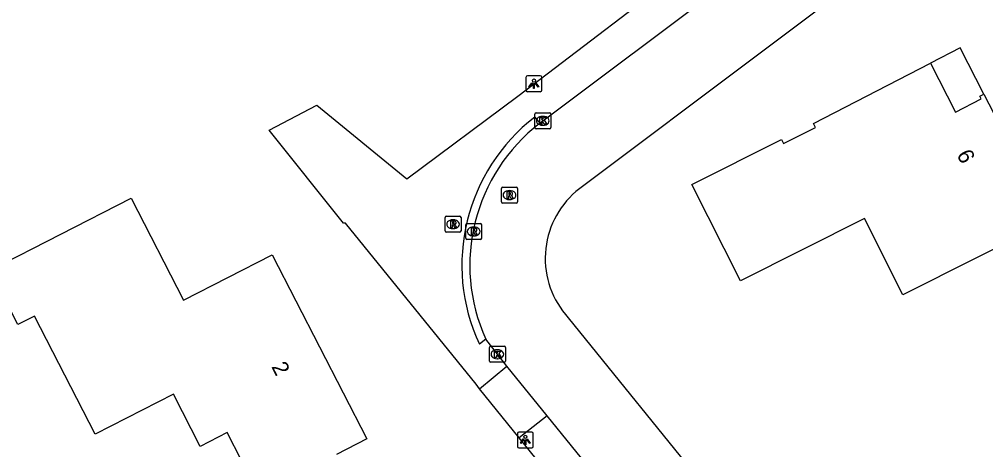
# Model space of a CAD drawing. Extents: x 162722 to 165099, y 384721 to 386283.
# Drawn here: x 163645.1 to 163705.8, y 384903 to 384930.1 of the extents above; entities that cross this region are included whole.
import ezdxf

# ---------------------------------------------------------------- set-up
doc = ezdxf.new("R2010")
doc.units = 0
for name, color, linetype in [('IMGEO_Kolk', 7, 'Continuous'), ('IMGEO_Lichtpunt', 7, 'Continuous'), ('IMGEO_Pand', 7, 'Continuous'), ('IMGEO_Pand_nummerreeks', 7, 'Continuous'), ('IMGEO_Pand_overbouw', 7, 'Continuous'), ('IMGEO_Rijbaan_lokaal_open', 7, 'Continuous'), ('IMGEO_Rioolput', 7, 'Continuous'), ('IMGEO_Voetpad_open', 7, 'Continuous')]:
    doc.layers.add(name, color=color, linetype=linetype)

msp = doc.modelspace()

# ---------------------------------------------------------------- linework, layer by layer
at = {"layer": 'IMGEO_Kolk'}
for p, q in [((163677.447, 384923.271), (163677.447, 384924.123)), ((163677.522, 384924.197), (163678.374, 384924.197)), ((163678.448, 384924.123), (163678.448, 384923.271)), ((163677.935, 384923.977), (163677.96, 384923.977)), ((163678.374, 384923.197), (163677.522, 384923.197)), ((163677.958, 384923.417), (163677.933, 384923.417)), ((163674.671, 384909.515), (163675.523, 384909.515)), ((163674.596, 384908.589), (163674.596, 384909.441)), ((163675.084, 384909.295), (163675.109, 384909.295)), ((163675.597, 384909.441), (163675.597, 384908.589)), ((163675.523, 384908.515), (163674.671, 384908.515)), ((163675.107, 384908.735), (163675.082, 384908.735))]:
    msp.add_line(p, q, dxfattribs=at)
for points in [[(163677.447, 384923.271), (163677.447, 384924.123)], [(163677.522, 384924.197), (163678.374, 384924.197)], [(163678.448, 384924.123), (163678.448, 384923.271)], [(163677.768, 384923.897), (163677.891, 384923.897), (163677.891, 384923.746), (163678.021, 384923.897), (163678.185, 384923.897), (163678.039, 384923.746), (163678.192, 384923.497), (163678.04, 384923.497), (163677.955, 384923.661), (163677.891, 384923.594), (163677.891, 384923.497), (163677.768, 384923.497), (163677.768, 384923.897)], [(163678.374, 384923.197), (163677.522, 384923.197)], [(163674.671, 384909.515), (163675.523, 384909.515)], [(163674.596, 384908.589), (163674.596, 384909.441)], [(163674.917, 384909.215), (163675.04, 384909.215), (163675.04, 384909.064), (163675.17, 384909.215), (163675.334, 384909.215), (163675.188, 384909.064), (163675.341, 384908.815), (163675.189, 384908.815), (163675.104, 384908.979), (163675.04, 384908.912), (163675.04, 384908.815), (163674.917, 384908.815), (163674.917, 384909.215)], [(163675.597, 384909.441), (163675.597, 384908.589)], [(163675.523, 384908.515), (163674.671, 384908.515)]]:
    msp.add_lwpolyline(points, dxfattribs=at)
for centre, start, end in [((163677.524, 384924.121), 91.55205, 178.44795), ((163677.524, 384924.121), 91.55205, 178.44795), ((163678.372, 384924.121), 1.55205, 88.44795), ((163678.372, 384924.121), 1.55205, 88.44795), ((163677.524, 384923.273), 181.55205, 268.44795), ((163677.524, 384923.273), 181.55205, 268.44795), ((163678.372, 384923.273), 271.55205, 358.44795), ((163678.372, 384923.273), 271.55205, 358.44795), ((163674.673, 384909.439), 91.55205, 178.44795), ((163674.673, 384909.439), 91.55205, 178.44795), ((163675.521, 384909.439), 1.55205, 88.44795), ((163675.521, 384909.439), 1.55205, 88.44795), ((163674.673, 384908.591), 181.55205, 268.44795), ((163674.673, 384908.591), 181.55205, 268.44795), ((163675.521, 384908.591), 271.55205, 358.44795), ((163675.521, 384908.591), 271.55205, 358.44795)]:
    msp.add_arc(centre, 0.0765, start, end, dxfattribs=at)
for centre, major_axis, ratio, start_param, end_param in [((163677.934, 384923.697), (-0.387, 0.002), 0.722429, 4.712389, 7.853982), ((163677.959, 384923.697), (-0.39, 0.002), 0.717154, 1.570796, 4.712389), ((163675.083, 384909.015), (-0.387, 0.002), 0.722429, 4.712389, 7.853982), ((163675.108, 384909.015), (-0.39, 0.002), 0.717154, 1.570796, 4.712389)]:
    msp.add_ellipse(centre, major_axis=major_axis, ratio=ratio, start_param=start_param, end_param=end_param, dxfattribs=at)
at = {"layer": 'IMGEO_Lichtpunt'}
for p, q in [((163677.793, 384926.527), (163676.985, 384926.527)), ((163677.793, 384926.527), (163676.985, 384926.527)), ((163676.891, 384926.432), (163676.891, 384925.625)), ((163676.891, 384926.432), (163676.891, 384925.625)), ((163677.887, 384925.625), (163677.887, 384926.432)), ((163677.887, 384925.625), (163677.887, 384926.432)), ((163676.985, 384925.531), (163677.793, 384925.531)), ((163676.985, 384925.531), (163677.793, 384925.531)), ((163677.253, 384904.119), (163676.445, 384904.119)), ((163677.253, 384904.119), (163676.445, 384904.119)), ((163676.351, 384904.024), (163676.351, 384903.217)), ((163676.351, 384904.024), (163676.351, 384903.217)), ((163677.347, 384903.217), (163677.347, 384904.024)), ((163677.347, 384903.217), (163677.347, 384904.024)), ((163676.445, 384903.123), (163677.253, 384903.123)), ((163676.445, 384903.123), (163677.253, 384903.123))]:
    msp.add_line(p, q, dxfattribs=at)
for points in [[(163677.265, 384926.096), (163677.304, 384926.068), (163677.116, 384925.806), (163677.078, 384925.833), (163677.265, 384926.096)], [(163677.367, 384926.048), (163677.414, 384926.048), (163677.414, 384925.726), (163677.367, 384925.726), (163677.367, 384926.048)], [(163677.477, 384926.068), (163677.515, 384926.095), (163677.702, 384925.833), (163677.663, 384925.805), (163677.477, 384926.068)], [(163676.725, 384903.688), (163676.764, 384903.66), (163676.576, 384903.398), (163676.538, 384903.425), (163676.725, 384903.688)], [(163676.827, 384903.64), (163676.874, 384903.64), (163676.874, 384903.318), (163676.827, 384903.318), (163676.827, 384903.64)], [(163676.937, 384903.66), (163676.975, 384903.687), (163677.162, 384903.425), (163677.123, 384903.397), (163676.937, 384903.66)]]:
    msp.add_lwpolyline(points, dxfattribs=at)
for centre in [(163677.39, 384926.23), (163676.85, 384903.822)]:
    msp.add_circle(centre, 0.0994, dxfattribs=at)
for centre, start, end in [((163676.985, 384926.432), 90, 180), ((163676.985, 384926.432), 90, 180), ((163677.793, 384926.432), 0, 90), ((163677.793, 384926.432), 0, 90), ((163676.985, 384925.625), 180, 270), ((163676.985, 384925.625), 180, 270), ((163677.793, 384925.625), 270, 0), ((163677.793, 384925.625), 270, 360), ((163676.445, 384904.024), 90, 180), ((163676.445, 384904.024), 90, 180), ((163677.253, 384904.024), 0, 90), ((163677.253, 384904.024), 0, 90), ((163676.445, 384903.217), 180, 270), ((163676.445, 384903.217), 180, 270), ((163677.253, 384903.217), 270, 0), ((163677.253, 384903.217), 270, 360)]:
    msp.add_arc(centre, 0.0946, start, end, dxfattribs=at)
at = {"layer": 'IMGEO_Pand'}
for points in [[(163700.576, 384912.76), (163698.165, 384917.548), (163690.367, 384913.622), (163687.312, 384919.691), (163692.94, 384922.524), (163693.071, 384922.265), (163695.08, 384923.277), (163694.949, 384923.535), (163702.295, 384927.318), (163703.875, 384924.249), (163705.494, 384925.083), (163705.411, 384925.243), (163705.661, 384925.37), (163709.772, 384917.389), (163700.576, 384912.76)], [(163659.924, 384900.579), (163658.124, 384904.091), (163656.423, 384903.219), (163654.742, 384906.499), (163649.828, 384903.98), (163646.017, 384911.417), (163644.976, 384910.883), (163643.226, 384914.296), (163652.091, 384918.839), (163655.38, 384912.42), (163660.955, 384915.277), (163666.893, 384903.689), (163664.992, 384902.715)]]:
    msp.add_lwpolyline(points, dxfattribs=at)
at = {"layer": 'IMGEO_Pand_overbouw'}
msp.add_lwpolyline([(163704.162, 384928.28), (163702.295, 384927.318), (163703.875, 384924.249), (163705.494, 384925.083), (163705.411, 384925.243), (163705.661, 384925.37)], close=True, dxfattribs=at)
at = {"layer": 'IMGEO_Rijbaan_lokaal_open'}
for points in [[(163677.764, 384923.542), (163677.956, 384923.704), (163689.321, 384932.243), (163699.74, 384940.081), (163700.468, 384940.621)], [(163703.684, 384937.056), (163680.028, 384919.248)], [(163679.55, 384911.309), (163688.362, 384900.411), (163688.262, 384900.349), (163695.837, 384890.93), (163705.052, 384879.586)], [(163675.679, 384908.261), (163674.367, 384909.96)], [(163678.232, 384905.132), (163675.679, 384908.261)], [(163688.814, 384892.037), (163684.328, 384897.597), (163678.232, 384905.132)]]:
    msp.add_lwpolyline(points, dxfattribs=at)
for centre, radius, start, end in [((163684.63, 384914.609), 11.267, 127.54713, 204.36847), ((163683.649, 384915.046), 5.547, 130.74979, 222.35907)]:
    msp.add_arc(centre, radius, start, end, dxfattribs=at)
at = {"layer": 'IMGEO_Rioolput'}
for p, q in [((163675.355, 384918.598), (163675.355, 384919.45)), ((163675.43, 384919.524), (163676.282, 384919.524)), ((163675.843, 384919.304), (163675.868, 384919.304)), ((163676.356, 384919.45), (163676.356, 384918.598)), ((163675.866, 384918.744), (163675.841, 384918.744)), ((163676.282, 384918.524), (163675.43, 384918.524)), ((163671.809, 384916.767), (163671.809, 384917.619)), ((163671.884, 384917.693), (163672.736, 384917.693)), ((163672.297, 384917.473), (163672.322, 384917.473)), ((163672.81, 384917.619), (163672.81, 384916.767)), ((163672.32, 384916.913), (163672.295, 384916.913)), ((163673.106, 384916.309), (163673.106, 384917.161)), ((163673.181, 384917.235), (163674.033, 384917.235)), ((163673.594, 384917.015), (163673.619, 384917.015)), ((163674.107, 384917.161), (163674.107, 384916.309)), ((163672.736, 384916.693), (163671.884, 384916.693)), ((163674.033, 384916.235), (163673.181, 384916.235)), ((163673.617, 384916.455), (163673.592, 384916.455))]:
    msp.add_line(p, q, dxfattribs=at)
for points in [[(163675.355, 384918.598), (163675.355, 384919.45)], [(163675.43, 384919.524), (163676.282, 384919.524)], [(163675.944, 384919.222), (163675.692, 384919.224), (163675.692, 384918.824)], [(163676.356, 384919.45), (163676.356, 384918.598)], [(163675.692, 384918.824), (163675.816, 384918.824), (163675.816, 384918.986), (163675.827, 384918.986)], [(163675.87, 384919.143), (163675.816, 384919.143), (163675.816, 384919.062)], [(163675.816, 384919.062), (163675.868, 384919.062)], [(163675.874, 384918.957), (163675.945, 384918.824), (163676.085, 384918.824), (163676.02, 384918.95)], [(163676.282, 384918.524), (163675.43, 384918.524)], [(163671.809, 384916.767), (163671.809, 384917.619)], [(163671.884, 384917.693), (163672.736, 384917.693)], [(163672.398, 384917.391), (163672.146, 384917.393), (163672.146, 384916.993)], [(163672.81, 384917.619), (163672.81, 384916.767)], [(163672.146, 384916.993), (163672.27, 384916.993), (163672.27, 384917.155), (163672.281, 384917.155)], [(163672.324, 384917.312), (163672.27, 384917.312), (163672.27, 384917.231)], [(163672.27, 384917.231), (163672.322, 384917.231)], [(163672.328, 384917.126), (163672.399, 384916.993), (163672.539, 384916.993), (163672.474, 384917.119)], [(163673.106, 384916.309), (163673.106, 384917.161)], [(163673.181, 384917.235), (163674.033, 384917.235)], [(163673.695, 384916.933), (163673.443, 384916.935), (163673.443, 384916.535)], [(163673.621, 384916.854), (163673.567, 384916.854), (163673.567, 384916.773)], [(163674.107, 384917.161), (163674.107, 384916.309)], [(163672.736, 384916.693), (163671.884, 384916.693)], [(163674.033, 384916.235), (163673.181, 384916.235)], [(163673.443, 384916.535), (163673.567, 384916.535), (163673.567, 384916.697), (163673.578, 384916.697)], [(163673.567, 384916.773), (163673.619, 384916.773)], [(163673.625, 384916.668), (163673.696, 384916.535), (163673.836, 384916.535), (163673.771, 384916.661)]]:
    msp.add_lwpolyline(points, dxfattribs=at)
for centre, radius, start, end in [((163675.432, 384919.448), 0.0765, 91.55205, 178.44795), ((163675.432, 384919.448), 0.0765, 91.55205, 178.44795), ((163675.943, 384919.112), 0.109, 350.36119, 89.41601), ((163676.28, 384919.448), 0.0765, 1.55205, 88.44795), ((163676.28, 384919.448), 0.0765, 1.55205, 88.44795), ((163675.826, 384918.933), 0.0533, 26.02933, 88.69889), ((163675.852, 384919.251), 0.19, 274.7715, 282.96867), ((163675.876, 384919.047), 0.0964, 77.00612, 93.18647), ((163675.89, 384919.104), 0.0378, 276.66336, 79.67722), ((163675.941, 384919.112), 0.112, 277.58423, 350.98172), ((163675.925, 384918.897), 0.108, 29.51342, 73.79051), ((163675.432, 384918.6), 0.0765, 181.55205, 268.44795), ((163675.432, 384918.6), 0.0765, 181.55205, 268.44795), ((163676.28, 384918.6), 0.0765, 271.55205, 358.44795), ((163676.28, 384918.6), 0.0765, 271.55205, 358.44795), ((163671.886, 384917.617), 0.0765, 91.55205, 178.44795), ((163671.886, 384917.617), 0.0765, 91.55205, 178.44795), ((163672.397, 384917.281), 0.109, 350.36119, 89.41601), ((163672.734, 384917.617), 0.0765, 1.55205, 88.44795), ((163672.734, 384917.617), 0.0765, 1.55205, 88.44795), ((163672.28, 384917.102), 0.0533, 26.02933, 88.69889), ((163672.306, 384917.42), 0.19, 274.7715, 282.96867), ((163672.33, 384917.216), 0.0964, 77.00612, 93.18647), ((163672.344, 384917.273), 0.0378, 276.66336, 79.67722), ((163672.395, 384917.281), 0.112, 277.58423, 350.98172), ((163672.379, 384917.066), 0.108, 29.51342, 73.79051), ((163673.183, 384917.159), 0.0765, 91.55205, 178.44795), ((163673.183, 384917.159), 0.0765, 91.55205, 178.44795), ((163673.627, 384916.758), 0.0964, 77.00612, 93.18647), ((163673.641, 384916.815), 0.0378, 276.66336, 79.67722), ((163673.694, 384916.823), 0.109, 350.36119, 89.41601), ((163673.692, 384916.823), 0.112, 277.58423, 350.98172), ((163674.031, 384917.159), 0.0765, 1.55205, 88.44795), ((163674.031, 384917.159), 0.0765, 1.55205, 88.44795), ((163671.886, 384916.769), 0.0765, 181.55205, 268.44795), ((163671.886, 384916.769), 0.0765, 181.55205, 268.44795), ((163672.734, 384916.769), 0.0765, 271.55205, 358.44795), ((163672.734, 384916.769), 0.0765, 271.55205, 358.44795), ((163673.183, 384916.311), 0.0765, 181.55205, 268.44795), ((163673.183, 384916.311), 0.0765, 181.55205, 268.44795), ((163673.577, 384916.644), 0.0533, 26.02933, 88.69889), ((163673.603, 384916.962), 0.19, 274.7715, 282.96867), ((163673.676, 384916.608), 0.108, 29.51342, 73.79051), ((163674.031, 384916.311), 0.0765, 271.55205, 358.44795), ((163674.031, 384916.311), 0.0765, 271.55205, 358.44795)]:
    msp.add_arc(centre, radius, start, end, dxfattribs=at)
for centre, major_axis, ratio, start_param, end_param in [((163675.842, 384919.024), (-0.387, 0.002), 0.722429, 4.712389, 7.853982), ((163675.867, 384919.024), (-0.39, 0.002), 0.717154, 1.570796, 4.712389), ((163672.296, 384917.193), (-0.387, 0.002), 0.722429, 4.712389, 7.853982), ((163672.321, 384917.193), (-0.39, 0.002), 0.717154, 1.570796, 4.712389), ((163673.593, 384916.735), (-0.387, 0.002), 0.722429, 4.712389, 7.853982), ((163673.618, 384916.735), (-0.39, 0.002), 0.717154, 1.570796, 4.712389)]:
    msp.add_ellipse(centre, major_axis=major_axis, ratio=ratio, start_param=start_param, end_param=end_param, dxfattribs=at)
at = {"layer": 'IMGEO_Voetpad_open'}
for points in [[(163673.969, 384906.848), (163673.753, 384907.134), (163665.55, 384917.268), (163665.421, 384917.261), (163660.75, 384923.114), (163663.751, 384924.681), (163669.399, 384920.052), (163676.37, 384925.254), (163699.363, 384942.796)], [(163677.445, 384923.927), (163677.764, 384923.542)], [(163674.367, 384909.96), (163673.962, 384909.644)], [(163673.969, 384906.848), (163675.679, 384908.261)], [(163676.468, 384903.753), (163673.969, 384906.848)], [(163678.232, 384905.132), (163676.468, 384903.753)], [(163687.084, 384890.632), (163676.468, 384903.753)]]:
    msp.add_lwpolyline(points, dxfattribs=at)
msp.add_arc((163684.629, 384914.609), 11.766, 127.63164, 204.95943, dxfattribs=at)

# ---------------------------------------------------------------- texts
at = {"layer": 'IMGEO_Pand_nummerreeks'}
for s, rotation, p in [('6', 297.25319, (163703.925, 384921.577)), ('2', 297.13181, (163660.878, 384908.233))]:
    msp.add_text(s, height=1, rotation=rotation, dxfattribs=at).set_placement(p)

doc.saveas('drawing.dxf')
